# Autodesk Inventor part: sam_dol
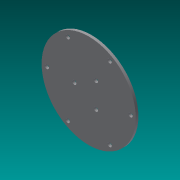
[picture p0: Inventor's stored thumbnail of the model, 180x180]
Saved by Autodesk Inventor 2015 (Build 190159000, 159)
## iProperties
Created: 2016-02
Part Number: sam_dol
Material: Generic
Document SubType Name: Modeling
Designer: Rafał
Density: 1 g/cm^3
Appearance: Default
Author: Rafał
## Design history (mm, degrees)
sketch "Sketch1" dims "d1" = 55, "d7" = 160
  geometry: C1 r 90 at (0, 0); C2 r 4 at (27.5, 0); C3 r 4 at (-13.75, 23.816); C4 r 4 at (-13.75, -23.816); C5 r 4 at (80, 0); C6 r 4 at (40, 69.282); C7 r 4 at (-40, 69.282); C8 r 4 at (-80, 0); C9 r 4 at (-40, -69.282); C10 r 4 at (40, -69.282); 3 further points
  constraints: 10 centre point, 3 coincident, 2 horizontal alignment, 24 other
  dimensions: "d0" = 180 diameter of C1; "d2" = 8 diameter of C2; "d5" = 360 deg dimension on point (0, 0) C2.centre (derived); "d8" = 8 diameter of C5; "d11" = 360 deg dimension on point (0, 0) C5.centre (derived)
extrude "Extrusion1" new body sketch "Sketch1" distance "d13" = 5; taper "d14" = 0 deg
body "Solid1"
